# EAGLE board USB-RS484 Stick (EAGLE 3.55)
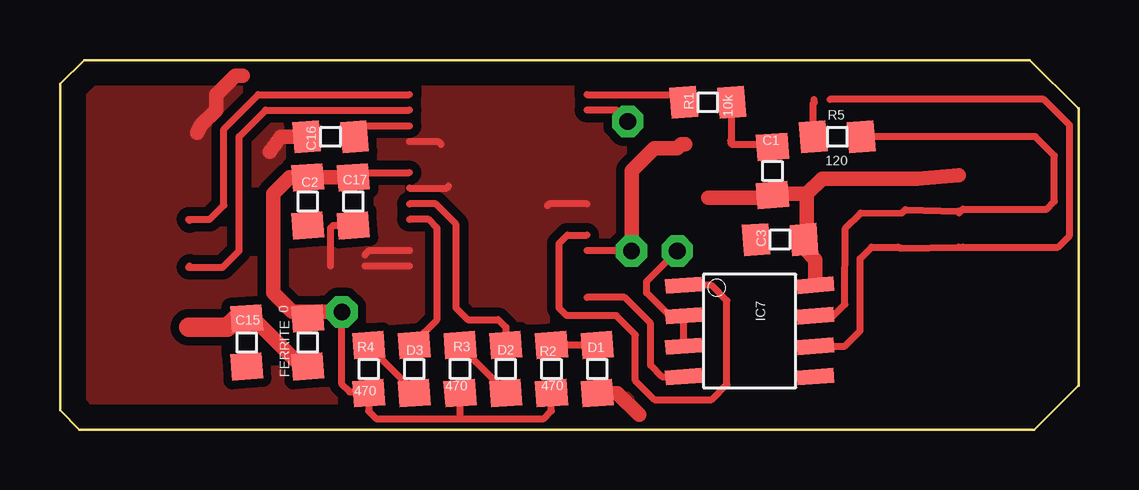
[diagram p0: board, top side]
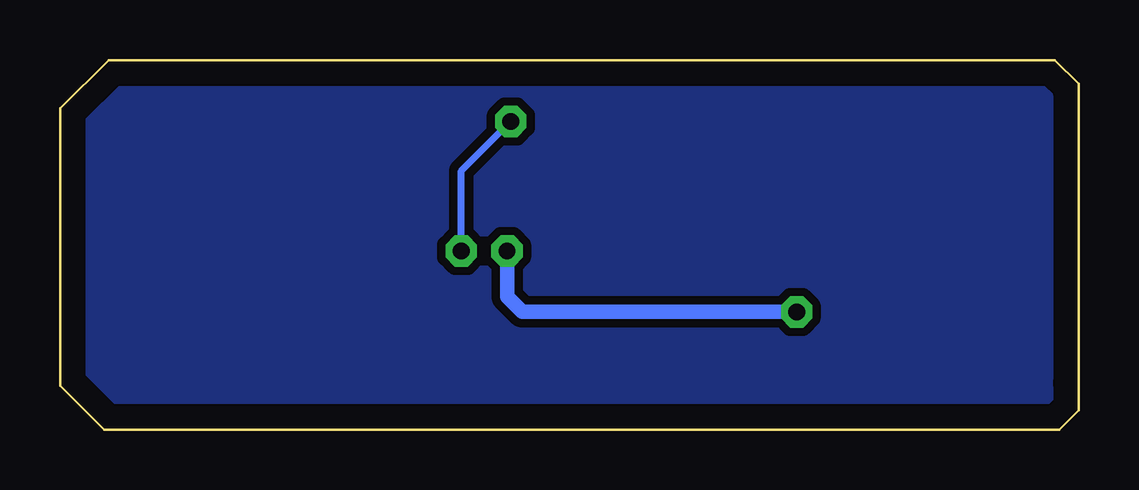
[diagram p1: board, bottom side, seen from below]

Size 42.44 x 15.4 mm. Coordinates in mm from the lower left corner, seen from the top.
Outline: 0,1.93 0,0.82 0,0.8 0.8,0 40.6,0 42.42,1.82 42.44,1.82 42.44,13.38 42.42,13.38 40.4,15.4 1,15.4 0,14.4 0,14.07 0,14.27 0,1.93
Copper layers used: Top, Bottom

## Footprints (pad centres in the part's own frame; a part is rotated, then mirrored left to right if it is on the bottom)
D0805 = smd 1.1 x 1.3 rotated 4.3:  -1,0 | smd 1.1 x 1.3 rotated 4.4:  1,0
8 = smd 0.61 x 1.524 rotated 4.3:  -2.54,-2.743 | smd 0.61 x 1.524 rotated 4.9:  -2.54,2.743 | smd 0.61 x 1.524 rotated 4.4:  -1.27,-2.743 | smd 0.61 x 1.524 rotated 4.5:  0,-2.743 | smd 0.61 x 1.524 rotated 4.8:  -1.27,2.743 | smd 0.61 x 1.524 rotated 4.7:  0,2.743;  1.27,2.743 | smd 0.61 x 1.524 rotated 4.6:  1.27,-2.743

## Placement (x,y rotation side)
C1  100n  [D0805]  29.69,10.78 270 top
C2  4,7æ  [D0805]  10.32,9.51 90 top
C3  100n  [D0805]  30,7.92 0 top
C15  100n  [D0805]  7.78,3.63 90 top
C16  100n  [D0805]  11.27,12.21 0 top
C17  100n  [D0805]  12.22,9.51 90 top
D1  Power  [D0805]  22.38,2.52 270 top
D2  RX_LED  [D0805]  18.57,2.52 90 top
D3  TX_LED  [D0805]  14.76,2.52 90 top
FERRITE  0  [D0805]  10.32,3.63 270 top
GND2  GND  [D]  8.73,11.57 0 top
GND3  GND  [D]  40.8,2.36 0 top
GND21  GND  [D]  11.27,6.81 0 top
GND22  GND  [D]  18.57,10.78 0 top
GND24  GND  [D]  6.51,13.95 0 top
IC2  FT232RL  [OP28]  18.26,9.51 90 top
IC7  MAX-485  [8]  28.73,3.47 270 top
J1  SMDJ1  [D-J2]  31.75,13.63 180 top
JP4  RS485  [L1,5X5]  37.94,7.6 270 top
R1  10k  [D0805]  26.99,13.63 180 top
R2  470  [D0805]  20.48,2.52 270 top
R3  470  [D0805]  16.67,2.52 270 top
R4  470  [D0805]  12.86,2.52 270 top
R5  120  [D0805]  32.39,12.2 0 top
ST1  USB-A  [B-A]  0.01,7.76 270 top
T4  IRLML6402  [T23(MO]  26.99,10.78 0 top

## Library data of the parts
C1-C3 C15-C17 D1-D3 FERRITE GND2 GND3 GND21 GND22 GND24 IC2 J1 JP4 R1-R5 ST1 T4 = CONTR1
IC7 = CONTR

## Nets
#POWEREN: IC2. R1.
+5V: C2. C17. FERRITE. IC2. R2. R3. R4. T4.
GND: C2. C3. C15. C16. C17. D1. GND2. GND3. GND21. GND22. GND24. IC2. IC7. JP4. ST1.
N$1: D1. R2.
N$2: D2. R3.
N$3: D3. R4.
N$4: C1. C3. IC7. JP4. T4.
N$5: C1. R1. T4.
N$6: IC7. JP4. R5.
N$7: IC2. IC7.
N$8: IC2. IC7.
N$9: IC2. IC7.
N$10: IC7. J1. JP4.
N$11: J1. R5.
N$12: D3. IC2.
N$13: D2. IC2.
N$18: C15. FERRITE. ST1.
N$20: IC2. ST1.
N$21: IC2. ST1.
N$30: C16. IC2.

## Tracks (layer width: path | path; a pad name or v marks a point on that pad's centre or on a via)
#POWEREN
  Top 0.3: 25.88,13.63 | 25.88,13.63 R1. | 21.96,13.96 25.55,13.96 25.88,13.63
+5V  (via drill 0.7 pad 1.3)
  Top 0.3: 21.96,7.46 23.8,7.46 v23.81,7.44 | C17. 12.22,10.62 12.31,10.71 14.56,10.71 | 16.67,0.46 13.18,0.46 12.86,0.77 R4. 12.75,1.52 12.7,1.57 12.06,1.57 11.75,1.89 v11.75,4.9 | 16.67,1.57 | 16.67,1.57 R3. | 16.67,0.46 16.67,1.57 | R2. 20.48,0.77 20.16,0.46 16.67,0.46
  Top 0.406: C2. 10.21,10.51
  Top 0.61: 10.32,4.9 10.32,4.63 | v11.75,4.9 10.32,4.9 | v23.81,7.44 23.81,10.78 24.77,11.73 25.72,11.73 25.88,11.89 26.05,11.89 | C2. 9.57,10.51 8.89,9.82 8.89,5.7 9.68,4.9 10.32,4.9 | C17. 11.79,10.51 10.21,10.51
  Bottom 0.61: v11.75,4.9 23.18,4.9 23.81,5.54 v23.81,7.44
GND
  Top 0.3: 14.56,12.01 15.76,12.01 15.88,11.89 | 14.56,10.06 16.11,10.06 16.19,10.14 | 14.56,6.81 12.7,6.81 | 12.22,8.51 11.38,8.51 11.27,8.39 11.27,6.81 | 11.27,6.81 | 21.96,9.41 20.38,9.41 20.32,9.35 | 14.56,7.46 12.87,7.46 12.7,7.28
  Top 0.61: 10.27,12.21 9.21,12.21 8.73,11.57 | 5.71,12.36 | D1. 23.23,1.52 24.13,0.62 | 6.51,13.95 | 5.71,12.36 5.87,12.68 6.51,13.32 6.51,13.95 | 6.51,13.95 7.3,14.74 7.62,14.74
  pour Top (isolate 0.356): 0.48,14.9 0.48,0.5 40.5,0.5 42,2 42,13.2 40.3,14.9
  pour Bottom (isolate 0.356): 0.48,14.9 0.48,0.5 40.5,0.5 42,2 42,13.2 40.3,14.9
N$1
  Top 0.3: 20.48,3.52 20.59,3.52 20.64,3.47 20.68,3.52 22.38,3.52
N$2
  Top 0.3: 18.57,1.52 18.57,1.57 16.67,3.47 16.67,3.52
N$3
  Top 0.3: 14.76,1.52 14.76,1.57 12.86,3.47 12.86,3.52
N$4
  Top 0.61: 27.01,9.66 29.52,9.66 29.64,9.78 C1. 29.96,9.78 30,9.82 31.11,9.82 | 31.11,9.82 | 31.11,9.82 31.75,10.46 35.72,10.46 37.44,10.6 | 31.11,9.82 31.11,7.92 31,7.81 C3. 31,7.55 31.48,7.08 31.48,6.01
N$5
  Top 0.3: 27.99,13.63 27.99,12.09 27.94,12.05 27.98,12.01 27.98,11.89 29.52,11.89 29.64,11.78 29.69,11.78
N$6
  Top 0.3: 31.48,4.74 32.23,4.74 32.7,5.22 32.72,8.38 33.36,9.02 35.08,9.03 35.22,9.17 37.44,9.1 37.44,9.05 37.47,9.03 37.62,9.19 41.12,9.19 41.43,9.51 41.43,11.41 40.64,12.21 R5.
N$7
  Top 0.3: 21.96,8.11 21.14,8.11 20.8,7.76 20.8,5.06 21.11,4.74 23.18,4.74 23.97,3.95 23.97,2.05 24.77,1.25 27.15,1.25 27.78,1.89 27.78,5.38 27.15,6.01 25.99,6.01
N$8
  Top 0.3: 21.96,5.51 23.53,5.51 24.61,4.43 24.61,2.68 25.08,2.2 25.99,2.2
N$9  (via drill 0.7 pad 1.3)
  Top 0.3: 25.99,3.47 25.99,4.54 26.04,4.59 25.99,4.63 25.99,4.74 25.4,4.74 24.45,5.7 24.45,6.17 v25.72,7.44 | 21.96,13.31 23.19,13.31 v23.65,12.84
  Bottom 0.3: v25.72,7.44 25.72,10.78 v23.65,12.84
N$10
  Top 0.3: 31.48,3.47 32.7,3.47 33.34,4.11 33.34,7.12 33.81,7.6 34.92,7.6 35.05,7.56 37.44,7.6 37.62,7.6 41.59,7.6 42.07,8.08 42.07,12.68 40.99,13.76 32.08,13.76
N$11
  Top 0.3: 31.42,13.76 31.42,13.65 31.43,13.63 31.39,13.59 31.39,12.21
N$12
  Top 0.3: 14.56,8.76 15.36,8.76 15.72,8.39 15.72,4.59 14.76,3.63 D3.
N$13
  Top 0.3: 14.56,9.41 15.66,9.41 16.51,8.55 16.51,5.06 16.99,4.59 18.26,4.59 18.57,4.27 D2.
N$18
  Top 0.61: FERRITE. 10,2.68 8.05,4.63 C15.
  Top 0.813: 7.78,4.59 | 7.78,4.59 C15. | 7.78,4.59 7.76,4.6 | 7.78,4.59 7.3,4.59 6.98,4.26 5.36,4.26
N$20
  Top 0.3: 14.56,13.31 8.56,13.31 7.46,12.21 7.46,7.44 6.78,6.76 5.4,6.76 | 5.36,6.76 5.4,6.76 | 5.4,6.76 5.4,6.81
N$21
  Top 0.3: 14.56,13.96 8.26,13.96 6.83,12.52 6.83,9.35 6.24,8.76 5.4,8.76 | 5.4,8.76 5.4,8.71 | 5.36,8.76 5.4,8.76 | 5.4,8.76
N$30
  Top 0.3: C16. 12.27,12.41 12.36,12.66 14.56,12.66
